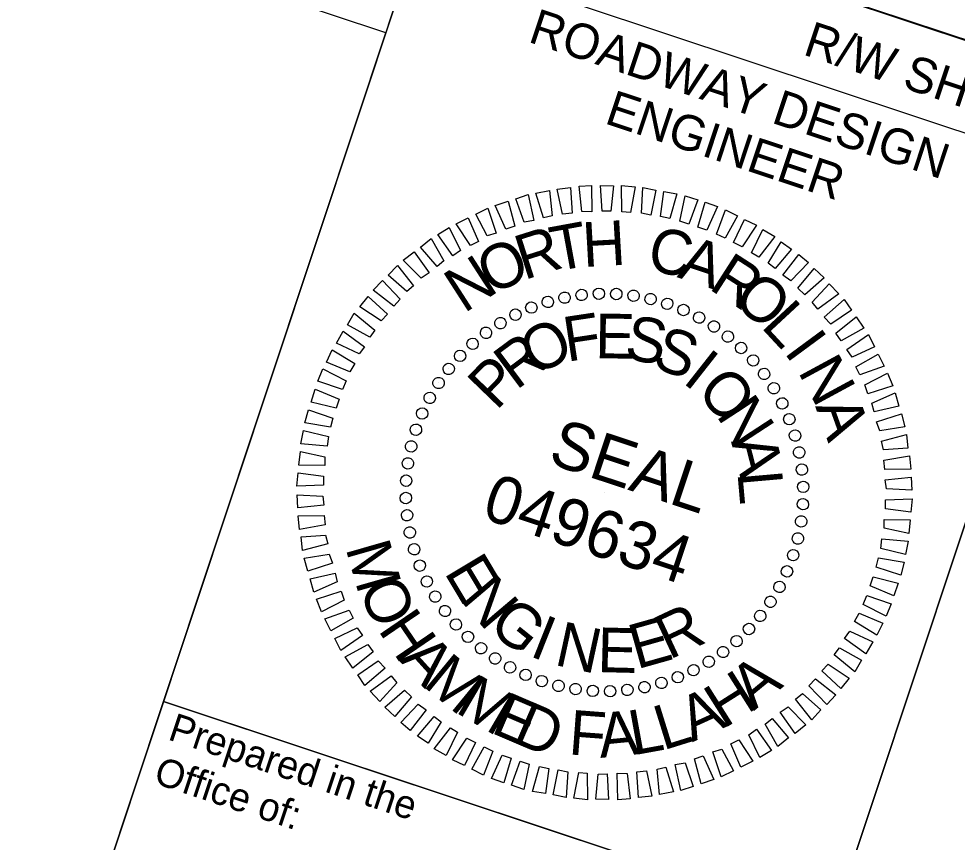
# Model space of a CAD drawing. Extents: x 2296288 to 2297455, y 600637 to 601606.
# Drawn here: x 2297286 to 2297365.9, y 601216.5 to 601286.7 of the extents above; entities that cross this region are included whole.
import ezdxf

# ---------------------------------------------------------------- set-up
doc = ezdxf.new("R2010")
doc.units = 0
for name, color, linetype in [('Default', 7, 'Continuous'), ('Exist DTM Drainline Cogo Comment', 7, 'Continuous'), ('Exist DTM Drainline Cogo Point CELL', 7, 'Continuous'), ('Exist Property Iron Pin Cogo Number', 7, 'Continuous'), ('Exist Roads Curbs Cogo Elevation', 7, 'Continuous'), ('Exist Roads EOP Cogo Comment', 7, 'Continuous'), ('Exist Roads EOP Other Cogo Number', 7, 'Continuous'), ('Exist Roads EOP Other Cogo Point CELL', 7, 'Continuous')]:
    doc.layers.add(name, color=color, linetype=linetype)

# ---------------------------------------------------------------- blocks, each defined once
blk = doc.blocks.new('POINT_DISPLAY')
at = {"layer": 'Default'}
blk.add_line((0, 0), (0, 0), dxfattribs=at)

msp = doc.modelspace()

# ---------------------------------------------------------------- linework, layer by layer
at = {"layer": 'Exist DTM Drainline Cogo Comment'}
msp.add_line((2297321.963, 601299.671), (2297435.862, 601261.8), dxfattribs=at)
msp.add_line((2297321.963, 601299.671), (2297435.862, 601261.8), dxfattribs=at)
for points in [[(2297326.705, 601313.933), (2297440.604, 601276.062), (2297435.862, 601261.8), (2297321.963, 601299.671)], [(2297319.596, 601292.554), (2297376.56, 601273.614), (2297355.263, 601209.561), (2297298.299, 601228.501)], [(2297376.56, 601273.614), (2297433.496, 601254.683), (2297412.199, 601190.63), (2297355.263, 601209.561)]]:
    msp.add_lwpolyline(points, close=True, dxfattribs=at)
at = {"layer": 'Exist DTM Drainline Cogo Point CELL'}
msp.add_lwpolyline([(2297421.637, 601266.561), (2296596.076, 601541.057), (2296406.768, 600971.704), (2297232.33, 600697.208)], close=True, dxfattribs=at)
at = {"layer": 'Exist Property Iron Pin Cogo Number'}
msp.add_lwpolyline([(2296425.754, 600981.215), (2297152.106, 600739.706), (2297168.672, 600769.147), (2297226.746, 600750.138), (2297369.397, 601166.292), (2297286.751, 601193.771), (2297317.24, 601285.466), (2296605.591, 601522.086)], close=True, dxfattribs=at)
at = {"layer": 'Exist Roads Curbs Cogo Elevation'}
msp.add_lwpolyline([(2296586.575, 601560.023), (2296387.821, 600962.212), (2297241.85, 600678.251), (2297402.771, 601162.301), (2297288.881, 601200.177), (2297326.705, 601313.933)], close=True, dxfattribs=at)
at = {"layer": 'Exist Roads EOP Other Cogo Number'}
for points in [[(2297333.938, 601270.25), (2297333.69, 601272.395), (2297334.746, 601272.471), (2297334.78, 601270.218)], [(2297335.656, 601270.282), (2297335.525, 601272.46), (2297336.615, 601272.418), (2297336.402, 601270.283)], [(2297337.342, 601270.22), (2297337.308, 601272.472), (2297338.472, 601272.335), (2297338.068, 601270.157)], [(2297329.007, 601269.328), (2297328.321, 601271.335), (2297329.367, 601271.698), (2297329.838, 601269.479)], [(2297330.66, 601269.702), (2297330.008, 601271.805), (2297331.182, 601272.019), (2297331.396, 601269.885)], [(2297332.293, 601270.014), (2297331.833, 601272.159), (2297332.975, 601272.277), (2297333.105, 601270.1)], [(2297339.007, 601270.094), (2297339.133, 601272.293), (2297340.234, 601272.07), (2297339.809, 601269.934)], [(2297340.62, 601269.807), (2297340.907, 601271.953), (2297342.017, 601271.761), (2297341.42, 601269.647)], [(2297327.458, 601268.739), (2297326.561, 601270.746), (2297327.649, 601271.131), (2297328.216, 601268.986)], [(2297342.274, 601269.435), (2297342.743, 601271.591), (2297343.8, 601271.24), (2297343.044, 601269.179)], [(2297343.813, 601268.923), (2297344.441, 601271.027), (2297345.498, 601270.675), (2297344.581, 601268.668)], [(2297325.879, 601268.162), (2297324.896, 601270.018), (2297325.92, 601270.532), (2297326.636, 601268.409)], [(2297345.393, 601268.326), (2297346.181, 601270.377), (2297347.185, 601269.865), (2297346.129, 601267.975)], [(2297324.439, 601267.361), (2297323.231, 601269.185), (2297324.256, 601269.698), (2297325.122, 601267.702)], [(2297346.856, 601267.591), (2297347.794, 601269.556), (2297348.808, 601269.076), (2297347.592, 601267.24)], [(2297322.934, 601266.473), (2297321.652, 601268.287), (2297322.634, 601268.885), (2297323.586, 601266.933)], [(2297348.382, 601266.727), (2297349.363, 601268.714), (2297350.377, 601268.127), (2297349.003, 601266.343)], [(2297321.6, 601265.565), (2297320.19, 601267.208), (2297321.108, 601267.935), (2297322.187, 601266.045)], [(2297349.792, 601265.832), (2297350.901, 601267.669), (2297351.798, 601267.05), (2297350.391, 601265.383)], [(2297320.235, 601264.56), (2297318.718, 601266.096), (2297319.636, 601266.823), (2297320.918, 601265.009)], [(2297351.052, 601264.808), (2297352.428, 601266.592), (2297353.23, 601265.899), (2297351.747, 601264.329)], [(2297319.008, 601263.438), (2297317.438, 601264.815), (2297318.217, 601265.658), (2297319.595, 601263.92)], [(2297352.324, 601263.709), (2297353.731, 601265.376), (2297354.576, 601264.597), (2297352.923, 601263.155)], [(2297317.91, 601262.167), (2297316.158, 601263.533), (2297316.936, 601264.377), (2297318.465, 601262.766)], [(2297353.563, 601262.515), (2297355.014, 601264.095), (2297355.825, 601263.221), (2297354.044, 601261.928)], [(2297316.822, 601260.929), (2297315.017, 601262.134), (2297315.731, 601262.998), (2297317.366, 601261.494)], [(2297354.567, 601261.256), (2297356.275, 601262.752), (2297356.894, 601261.835), (2297355.144, 601260.638)], [(2297315.862, 601259.541), (2297313.971, 601260.595), (2297314.548, 601261.578), (2297316.31, 601260.138)], [(2297355.572, 601259.89), (2297357.311, 601261.269), (2297357.952, 601260.309), (2297356.031, 601259.239)], [(2297314.967, 601258.129), (2297313.023, 601259.025), (2297313.609, 601260.04), (2297315.414, 601258.729)], [(2297356.491, 601258.482), (2297358.337, 601259.754), (2297358.85, 601258.729), (2297356.951, 601257.831)], [(2297314.167, 601256.582), (2297312.171, 601257.423), (2297312.66, 601258.471), (2297314.582, 601257.298)], [(2297357.283, 601257.009), (2297359.171, 601258.089), (2297359.684, 601257.065), (2297357.624, 601256.327)], [(2297313.528, 601255.087), (2297311.446, 601255.779), (2297311.872, 601256.846), (2297313.848, 601255.834)], [(2297358.052, 601255.473), (2297359.983, 601256.467), (2297360.411, 601255.4), (2297358.298, 601254.715)], [(2297312.995, 601253.485), (2297310.86, 601254.017), (2297311.222, 601255.106), (2297313.251, 601254.253)], [(2297358.639, 601253.925), (2297360.636, 601254.792), (2297360.935, 601253.66), (2297358.822, 601253.189)], [(2297312.527, 601251.862), (2297310.339, 601252.234), (2297310.636, 601253.344), (2297312.718, 601252.652)], [(2297359.037, 601252.335), (2297361.15, 601253.02), (2297361.45, 601251.889), (2297359.315, 601251.566)], [(2297312.24, 601250.251), (2297309.998, 601250.463), (2297310.232, 601251.593), (2297312.335, 601251.072)], [(2297359.444, 601250.67), (2297361.589, 601251.237), (2297361.706, 601250.096), (2297359.625, 601249.934)], [(2297312.048, 601248.606), (2297309.817, 601248.636), (2297309.955, 601249.8), (2297312.049, 601249.353)], [(2297359.658, 601249.07), (2297361.846, 601249.445), (2297361.965, 601248.303), (2297359.744, 601248.258)], [(2297311.922, 601246.941), (2297309.649, 601246.843), (2297309.776, 601247.975), (2297311.921, 601247.689)], [(2297359.777, 601247.393), (2297361.987, 601247.619), (2297362.04, 601246.499), (2297359.874, 601246.614)], [(2297311.955, 601245.222), (2297309.746, 601244.996), (2297309.692, 601246.118), (2297311.859, 601246.001)], [(2297359.809, 601245.675), (2297362.084, 601245.773), (2297361.956, 601244.641), (2297359.81, 601244.928)], [(2297312.075, 601243.547), (2297309.886, 601243.171), (2297309.768, 601244.314), (2297311.988, 601244.357)], [(2297359.683, 601244.01), (2297361.914, 601243.979), (2297361.776, 601242.815), (2297359.683, 601243.262)], [(2297312.289, 601241.945), (2297310.144, 601241.378), (2297310.025, 601242.52), (2297312.106, 601242.682)], [(2297359.492, 601242.366), (2297361.734, 601242.154), (2297361.5, 601241.022), (2297359.397, 601241.544)], [(2297312.696, 601240.28), (2297310.583, 601239.596), (2297310.283, 601240.726), (2297312.418, 601241.049)], [(2297359.205, 601240.753), (2297361.394, 601240.381), (2297361.096, 601239.271), (2297359.014, 601239.963)], [(2297313.092, 601238.69), (2297311.096, 601237.824), (2297310.796, 601238.955), (2297312.909, 601239.426)], [(2297358.737, 601239.13), (2297360.872, 601238.598), (2297360.51, 601237.509), (2297358.481, 601238.362)], [(2297313.681, 601237.143), (2297311.749, 601236.148), (2297311.321, 601237.216), (2297313.434, 601237.9)], [(2297358.204, 601237.528), (2297360.286, 601236.836), (2297359.86, 601235.769), (2297357.885, 601236.782)], [(2297314.45, 601235.606), (2297312.562, 601234.526), (2297312.048, 601235.551), (2297314.109, 601236.289)], [(2297357.565, 601236.034), (2297359.562, 601235.192), (2297359.071, 601234.146), (2297357.149, 601235.319)], [(2297315.241, 601234.134), (2297313.395, 601232.862), (2297312.882, 601233.886), (2297314.782, 601234.784)], [(2297356.765, 601234.486), (2297358.709, 601233.59), (2297358.122, 601232.575), (2297356.317, 601233.887)], [(2297316.16, 601232.725), (2297314.422, 601231.346), (2297313.78, 601232.307), (2297315.7, 601233.376)], [(2297355.87, 601233.076), (2297357.76, 601232.021), (2297357.185, 601231.038), (2297355.421, 601232.477)], [(2297317.164, 601231.36), (2297315.458, 601229.863), (2297314.837, 601230.781), (2297316.588, 601231.978)], [(2297354.911, 601231.687), (2297356.715, 601230.483), (2297356.001, 601229.617), (2297354.367, 601231.121)], [(2297318.168, 601230.101), (2297316.718, 601228.52), (2297315.907, 601229.394), (2297317.688, 601230.687)], [(2297353.822, 601230.447), (2297355.575, 601229.084), (2297354.795, 601228.239), (2297353.268, 601229.85)], [(2297319.408, 601228.906), (2297318, 601227.239), (2297317.157, 601228.018), (2297318.81, 601229.46)], [(2297352.723, 601229.177), (2297354.294, 601227.801), (2297353.516, 601226.957), (2297352.137, 601228.695)], [(2297320.679, 601227.808), (2297319.303, 601226.024), (2297318.503, 601226.717), (2297319.986, 601228.288)], [(2297351.497, 601228.055), (2297353.015, 601226.519), (2297352.097, 601225.793), (2297350.815, 601227.606)], [(2297321.939, 601226.784), (2297320.831, 601224.946), (2297319.934, 601225.566), (2297321.342, 601227.232)], [(2297350.131, 601227.05), (2297351.541, 601225.408), (2297350.625, 601224.682), (2297349.544, 601226.57)], [(2297323.349, 601225.888), (2297322.369, 601223.902), (2297321.354, 601224.488), (2297322.73, 601226.272)], [(2297348.798, 601226.142), (2297350.08, 601224.329), (2297349.099, 601223.73), (2297348.147, 601225.683)], [(2297324.877, 601225.024), (2297323.939, 601223.06), (2297322.924, 601223.539), (2297324.139, 601225.376)], [(2297326.339, 601224.289), (2297325.551, 601222.238), (2297324.548, 601222.75), (2297325.602, 601224.642)], [(2297347.293, 601225.256), (2297348.501, 601223.431), (2297347.477, 601222.918), (2297346.611, 601224.913)], [(2297327.92, 601223.693), (2297327.292, 601221.59), (2297326.235, 601221.941), (2297327.151, 601223.949)], [(2297344.273, 601223.876), (2297345.172, 601221.87), (2297344.083, 601221.484), (2297343.516, 601223.629)], [(2297345.853, 601224.453), (2297346.837, 601222.597), (2297345.812, 601222.083), (2297345.095, 601224.208)], [(2297329.457, 601223.182), (2297328.99, 601221.025), (2297327.933, 601221.377), (2297328.689, 601223.437)], [(2297331.112, 601222.81), (2297330.826, 601220.663), (2297329.716, 601220.854), (2297330.312, 601222.968)], [(2297341.072, 601222.913), (2297341.725, 601220.81), (2297340.551, 601220.596), (2297340.335, 601222.731)], [(2297342.726, 601223.287), (2297343.41, 601221.281), (2297342.365, 601220.917), (2297341.894, 601223.138)], [(2297332.724, 601222.522), (2297332.598, 601220.323), (2297331.498, 601220.547), (2297331.924, 601222.681)], [(2297334.39, 601222.395), (2297334.423, 601220.143), (2297333.26, 601220.28), (2297333.663, 601222.459)], [(2297336.077, 601222.333), (2297336.206, 601220.155), (2297335.117, 601220.196), (2297335.329, 601222.332)], [(2297337.795, 601222.366), (2297338.042, 601220.22), (2297336.985, 601220.145), (2297336.951, 601222.398)], [(2297339.439, 601222.601), (2297339.9, 601220.456), (2297338.757, 601220.338), (2297338.628, 601222.515)]]:
    msp.add_lwpolyline(points, close=True, dxfattribs=at)
for centre, major_axis in [((2297333.915, 601263.134), (-0.056, 0.483)), ((2297335.389, 601263.24), (-0.014, 0.486)), ((2297336.866, 601263.217), (0.029, 0.485)), ((2297331.024, 601262.541), (-0.139, 0.466)), ((2297332.457, 601262.901), (-0.098, 0.476)), ((2297338.335, 601263.066), (0.071, 0.481)), ((2297339.786, 601262.787), (0.113, 0.473)), ((2297341.206, 601262.382), (0.153, 0.461)), ((2297329.629, 601262.057), (-0.179, 0.452)), ((2297342.586, 601261.855), (0.193, 0.446)), ((2297326.99, 601260.735), (-0.255, 0.414)), ((2297328.28, 601261.454), (-0.218, 0.435)), ((2297343.915, 601261.21), (0.231, 0.428)), ((2297325.767, 601259.907), (-0.29, 0.39)), ((2297345.183, 601260.452), (0.268, 0.406)), ((2297346.38, 601259.586), (0.302, 0.381)), ((2297324.621, 601258.975), (-0.323, 0.363)), ((2297347.496, 601258.619), (0.334, 0.353)), ((2297323.56, 601257.947), (-0.353, 0.334)), ((2297348.524, 601257.558), (0.363, 0.323)), ((2297322.593, 601256.83), (-0.381, 0.302)), ((2297349.456, 601256.412), (0.39, 0.29)), ((2297321.727, 601255.633), (-0.406, 0.268)), ((2297350.285, 601255.189), (0.414, 0.255)), ((2297320.969, 601254.366), (-0.428, 0.231)), ((2297351.003, 601253.899), (0.435, 0.218)), ((2297320.324, 601253.037), (-0.446, 0.193)), ((2297351.606, 601252.55), (0.452, 0.179)), ((2297319.797, 601251.657), (-0.461, 0.153)), ((2297352.09, 601251.155), (0.466, 0.139)), ((2297319.392, 601250.236), (-0.473, 0.113)), ((2297352.45, 601249.722), (0.476, 0.098)), ((2297319.113, 601248.786), (-0.481, 0.071)), ((2297352.684, 601248.263), (0.483, 0.056)), ((2297318.962, 601247.316), (-0.485, 0.029)), ((2297352.79, 601246.79), (0.486, 0.014)), ((2297318.939, 601245.839), (-0.486, -0.014)), ((2297352.767, 601245.313), (0.485, -0.029)), ((2297319.044, 601244.366), (-0.483, -0.056)), ((2297352.615, 601243.844), (0.481, -0.071)), ((2297319.278, 601242.908), (-0.476, -0.098)), ((2297352.336, 601242.393), (0.473, -0.113)), ((2297319.638, 601241.475), (-0.466, -0.139)), ((2297351.932, 601240.972), (0.461, -0.153)), ((2297320.122, 601240.079), (-0.452, -0.179)), ((2297351.405, 601239.592), (0.446, -0.193)), ((2297320.725, 601238.731), (-0.435, -0.218)), ((2297350.76, 601238.264), (0.428, -0.231)), ((2297321.444, 601237.44), (-0.414, -0.255)), ((2297350.001, 601236.996), (0.406, -0.268)), ((2297322.272, 601236.217), (-0.39, -0.29)), ((2297349.135, 601235.799), (0.381, -0.302)), ((2297323.204, 601235.071), (-0.363, -0.323)), ((2297348.168, 601234.683), (0.353, -0.334)), ((2297324.232, 601234.01), (-0.334, -0.353)), ((2297347.108, 601233.655), (0.323, -0.363)), ((2297325.349, 601233.043), (-0.302, -0.381)), ((2297345.962, 601232.723), (0.29, -0.39)), ((2297326.545, 601232.177), (-0.268, -0.406)), ((2297327.813, 601231.419), (-0.231, -0.428)), ((2297343.448, 601231.176), (0.218, -0.435)), ((2297344.739, 601231.894), (0.255, -0.414)), ((2297329.142, 601230.774), (-0.193, -0.446)), ((2297342.1, 601230.572), (0.179, -0.452)), ((2297330.522, 601230.247), (-0.153, -0.461)), ((2297331.943, 601229.843), (-0.113, -0.473)), ((2297333.393, 601229.564), (-0.071, -0.481)), ((2297339.271, 601229.729), (0.098, -0.476)), ((2297340.704, 601230.089), (0.139, -0.466)), ((2297334.863, 601229.412), (-0.029, -0.485)), ((2297336.34, 601229.389), (0.014, -0.486)), ((2297337.813, 601229.495), (0.056, -0.483))]:
    msp.add_ellipse(centre, major_axis=major_axis, ratio=0.999708, dxfattribs=at)
at = {"layer": 'Exist Roads EOP Other Cogo Point CELL'}
msp.add_lwpolyline([(2297298.299, 601228.501), (2297412.17, 601190.64), (2297407.201, 601175.695), (2297293.33, 601213.557)], close=True, dxfattribs=at)

# ---------------------------------------------------------------- block references
at = {"layer": 'Exist Roads EOP Other Cogo Number', "xscale": 41.41195952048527, "yscale": 41.4119595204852, "rotation": -18.391327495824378}
for p in [(2297332.459, 601262.916), (2297333.921, 601263.141), (2297335.383, 601263.258), (2297336.868, 601263.228), (2297338.34, 601263.058), (2297329.621, 601262.081), (2297331.019, 601262.54), (2297339.782, 601262.793), (2297341.213, 601262.387), (2297328.276, 601261.46), (2297342.6, 601261.856), (2297326.974, 601260.755), (2297343.914, 601261.205), (2297345.196, 601260.459), (2297325.768, 601259.911), (2297324.605, 601258.981), (2297346.403, 601259.594), (2297347.503, 601258.625), (2297323.549, 601257.944), (2297348.539, 601257.569), (2297322.578, 601256.844), (2297349.469, 601256.406), (2297321.715, 601255.638), (2297350.313, 601255.201), (2297320.968, 601254.355), (2297351.019, 601253.899), (2297320.319, 601253.042), (2297351.639, 601252.554), (2297319.786, 601251.655), (2297352.098, 601251.156), (2297319.381, 601250.223), (2297352.473, 601249.715), (2297319.115, 601248.782), (2297352.699, 601248.252), (2297318.946, 601247.309), (2297335.867, 601246.308), (2297352.817, 601246.79), (2297318.915, 601245.825), (2297352.787, 601245.307), (2297352.351, 601242.392), (2297319.633, 601241.459), (2297351.947, 601240.962), (2297320.094, 601240.061), (2297351.414, 601239.573), (2297320.714, 601238.718), (2297350.763, 601238.26), (2297321.42, 601237.416), (2297350.018, 601236.979), (2297322.264, 601236.209), (2297349.154, 601235.771), (2297323.193, 601235.048), (2297348.183, 601234.671), (2297324.229, 601233.991), (2297347.127, 601233.634), (2297325.33, 601233.021), (2297345.964, 601232.705), (2297326.537, 601232.157), (2297344.758, 601231.86), (2297327.818, 601231.41), (2297343.457, 601231.156), (2297329.131, 601230.761), (2297330.52, 601230.228), (2297340.714, 601230.075), (2297342.112, 601230.536), (2297331.95, 601229.824), (2297333.392, 601229.557), (2297334.865, 601229.388), (2297336.349, 601229.357), (2297337.811, 601229.476), (2297339.273, 601229.701)]:
    msp.add_blockref('POINT_DISPLAY', p, dxfattribs=at)

# ---------------------------------------------------------------- texts
at = {"layer": 'Exist DTM Drainline Cogo Comment'}
for s, height, p in [('ROADWAY DESIGN', 3.00007, (2297329.26, 601284.725)), ('R/W SHEET NO.', 3.00007, (2297352.674, 601283.642)), ('ENGINEER', 3.0001, (2297335.773, 601277.786))]:
    msp.add_text(s, height=height, rotation=341.60824, dxfattribs=at).set_placement(p)
at = {"layer": 'Exist Roads EOP Cogo Comment'}
for s, height, p in [('Prepared in the ', 2.40001, (2297298.574, 601225.292)), ('Office of:', 2.4, (2297297.343, 601221.591))]:
    msp.add_text(s, height=height, rotation=341.60824, dxfattribs=at).set_placement(p)
at = {"layer": 'Exist Roads EOP Other Cogo Number'}
for s, height, rotation, p in [('T', 3.806, 10.42844, (2297331.627, 601265.113)), ('H', 3.806, 3.22815, (2297334.07, 601265.51)), ('R', 3.806, 17.62918, (2297329.005, 601264.387)), ('C', 3.806, 348.82854, (2297339.37, 601265.278)), ('O', 3.806, 24.83041, (2297326.159, 601263.095)), ('A', 3.806, 341.62899, (2297341.977, 601264.659)), ('N', 3.806, 32.76914, (2297323.886, 601261.529)), ('R', 3.806, 327.22977, (2297344.643, 601263.7)), ('O', 3.806, 320.02984, (2297346.642, 601262.535)), ('L', 3.806, 312.82955, (2297349.108, 601260.435)), ('F', 3.807, 8.57571, (2297332.662, 601257.439)), ('E', 3.807, 359.21974, (2297335.043, 601257.75)), ('S', 3.807, 349.86428, (2297337.459, 601257.731)), ('O', 3.807, 27.28991, (2297329.953, 601256.214)), ('S', 3.807, 340.50907, (2297339.787, 601257.028)), ('I', 3.806, 306.38924, (2297351.085, 601258.293)), ('R', 3.807, 36.64832, (2297328.329, 601254.974)), ('I', 3.807, 321.79828, (2297342.417, 601255.725)), ('N', 3.806, 298.42758, (2297352.289, 601256.639)), ('P', 3.807, 46.00756, (2297326.641, 601253.222)), ('O', 3.807, 312.44216, (2297343.584, 601254.835)), ('N', 3.807, 303.08528, (2297345.32, 601252.909)), ('A', 3.806, 289.67079, (2297353.8, 601253.654)), ('SEAL', 4.0496, 341.60867, (2297330.925, 601248.841)), ('A', 3.807, 284.36894, (2297346.636, 601250.652)), ('049634', 4.0508, 341.60867, (2297325.267, 601244.175)), ('L', 3.807, 275.00952, (2297347.181, 601248.016)), ('M', 3.807, 286.01937, (2297313.783, 601241.591)), ('E', 3.807, 300.88556, (2297322.152, 601239.521)), ('O', 3.807, 295.11545, (2297314.831, 601238.047)), ('N', 3.807, 310.24263, (2297323.514, 601237.179)), ('G', 3.807, 321.11188, (2297325.824, 601234.715)), ('R', 3.807, 25.09008, (2297341.37, 601232.032)), ('H', 3.807, 304.2738, (2297316.508, 601234.618)), ('I', 3.807, 338.30987, (2297329.37, 601232.423)), ('E', 3.807, 15.73276, (2297338.607, 601231.236)), ('N', 3.807, 347.66506, (2297331.493, 601231.646)), ('E', 3.807, 358.57554, (2297335.222, 601231.019)), ('A', 3.807, 312.15782, (2297318.303, 601232.048)), ('M', 3.807, 320.53409, (2297320.29, 601229.89)), ('A', 3.807, 39.48696, (2297348.586, 601227.687)), ('H', 3.807, 32.29177, (2297346.014, 601226.151)), ('M', 3.807, 329.62507, (2297323.049, 601227.649)), ('A', 3.807, 24.4875, (2297343.333, 601225.027)), ('E', 3.807, 336.75173, (2297326.073, 601225.897)), ('D', 3.807, 336.75173, (2297327.909, 601225.114)), ('F', 3.807, 355.69144, (2297332.739, 601224.009)), ('A', 3.807, 5.59209, (2297335.503, 601223.698)), ('L', 3.807, 10.33698, (2297338.318, 601223.919)), ('L', 3.807, 17.30223, (2297340.835, 601224.328))]:
    msp.add_text(s, height=height, rotation=rotation, dxfattribs=at).set_placement(p)

doc.saveas('drawing.dxf')
